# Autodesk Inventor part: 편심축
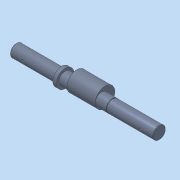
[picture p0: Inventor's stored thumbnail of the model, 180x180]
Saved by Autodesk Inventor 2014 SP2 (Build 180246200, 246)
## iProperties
Manager: 한국ATC센터
Company: 한국ATC센터
Created: 2014-10
Part Number: 편심축
Document SubType Name: Modeling
Designer: 한국ATC센터
Density: 7.86 g/cm^3
Material: 강, 연강
Mass: 1420.78 g
Surface Area: 286.549 cm^2
Volume: 180.761 cm^3
Appearance: 강철
Author: KYOUNG IL JANG
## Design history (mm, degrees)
sketch "스케치1"
  geometry: L1 (-142, 0)-(142, 0); L2 (-142, 0)-(-142, 12.5); L3 (-142, 12.5)-(-52, 12.5); L4 (-52, 12.5)-(-52, 17.5); L5 (-52, 17.5)-(-45, 17.5); L6 (-45, 17.5)-(-45, 12.5); L7 (-45, 12.5)-(48.65, 12.5); L8 (48.65, 12.5)-(48.65, 11.95); L9 (48.65, 11.95)-(50, 11.95); L10 (50, 11.95)-(50, 12.5); L11 (50, 12.5)-(142, 12.5); L12 (142, 12.5)-(142, 0); L13 (109, 12.5)-(109, 9.1); L14 (109, 9.1)-(134, 9.1); L15 (134, 9.1)-(134, 12.5); L16 (117, -12.5)-(119.5, -12.5); L17 (119.5, -12.5)-(117, -10); L18 (117, -10)-(117, -12.5); L19 (-109, 12.5)-(-109, 9.1); L20 (-109, 9.1)-(-134, 9.1); L21 (-134, 9.1)-(-134, 12.5); L22 (-117, -12.5)-(-117, -10); L23 (-117, -10)-(-114.5, -12.5); L24 (-114.5, -12.5)-(-117, -12.5); 2 further points
  constraints: 48 end point, 11 parallel, 8 perpendicular, 5 collinear, 4 point on line, 1 coincident, 1 horizontal, 1 midpoint, 1 vertical
  dimensions: "d0" = 284 distance of L1.start L1.end (derived); "d1" = 25 diameter of L3 L1; "d2" = 35 diameter of L5 L1; "d3" = 90 distance of L2.end L3.end; "d4" = 187 distance between parallel lines of L12 L6; "d6" = 1.35 distance of L8.end L9.end; "d7" = 23.9 diameter of L9 L1; "d8" = 3.4 distance between parallel lines of L14 L11; "d9" = 8 distance between parallel lines of L15 L12; "d10" = 25 distance of L13.end L14.end; "d11" = 25 diameter of L16 L1 (= d1); "d12" = 25 distance from line of L12 L16.start; "d13" = 45 deg angle of L17 L18; "d14" = 5 diameter of L16.end L18; "d27" = 92 distance between parallel lines of L10 L12; "d32" = 7 distance of L4.end L5.end; "d33" = 8 distance between parallel lines of L2 L21; "d34" = 25 distance between parallel lines of L21 L19; "d35" = 3.4 distance between parallel lines of L3 L20; "d36" = 25 distance from line of L22.start L2; "d37" = 5 diameter of L23.end L22
revolve "회전1" stored, may be unused: angle "d15" = 90 deg
revolve "회전2" stored, may be unused: angle "d16" = 90 deg
revolve "회전3" stored, may be unused: angle "d38" = 90 deg
extrude "돌출1" cut sketch "스케치1" stored distance "d17" = 8; taper "d18" = 0 deg
fillet "모깎기1" dims "d19" = 4
node "작업 평면1"
sketch "스케치2"
  geometry: L1 (12.99, -6.5)-(8.66, -14); L2 (-12.99, -6.5)-(-8.66, -14); C1 r 12.5 at (0, 0) reference; C2 r 19.5 at (0, 7); A1 r 15 centre (0, 1) between (12.99, -6.5) and (-12.99, -6.5); A2 r 10 centre (0, -9) between (-8.66, -14) and (8.66, -14); 1 further point
  constraints: 5 tangent, 4 end point, 4 point on circle, 3 centre point, 3 vertical alignment
  dimensions: "d21" = 7 distance of point (0, 0) C2.centre; "d30" = 39 diameter of C2 (derived); "d39" = 10 distance of A2.centre A1.centre; "d40" = 30 diameter of A1; "d41" = 20 diameter of A2; "d42" = 1 distance of point (0, 0) A1.centre
extrude "돌출2" join sketch "스케치2" distance "d22" = 56; taper "d23" = 0 deg
chamfer "모따기1" distance "d24" = 1; stored, may be unused: second distance "d25" = 2, angle "d26" = 45 deg
node "솔리드1"
other parameters: "d20" = 16
